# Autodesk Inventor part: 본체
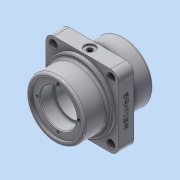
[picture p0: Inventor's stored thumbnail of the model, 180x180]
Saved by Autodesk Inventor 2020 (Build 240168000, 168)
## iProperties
Created: 2023-10
Part Number: 본체
Material: 알루미늄 6061
Document SubType Name: Modeling
Designer: CAD14
Density: 2.7 g/cm^3
Appearance: 흰색
Mass: 945.786 g
Surface Area: 536.974 cm^2
Volume: 350.291 cm^3
Author: CAD14
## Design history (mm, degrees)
sketch "스케치1"
  geometry: L1 (-45, 0)-(45, 0); L2 (-45, 38)-(45, 38); L3 (-45, 38)-(-45, 33); L4 (-45, 33)-(-41, 33); L5 (-41, 33)-(-41, 23.5); L6 (-41, 23.5)-(-24, 23.5); L7 (-24, 23.5)-(-24, 20.5); L8 (-24, 20.5)-(24, 20.5); L9 (24, 20.5)-(24, 23.5); L10 (24, 23.5)-(41, 23.5); L11 (41, 23.5)-(41, 33); L12 (41, 33)-(45, 33); L13 (45, 33)-(45, 38); 2 further points
  constraints: 26 end point, 10 perpendicular, 3 equal length, 2 horizontal, 2 vertical alignment, 1 coincident, 1 midpoint, 1 vertical
  dimensions: "d0" = 90 distance of L1.start L1.end; "d2" = 41 diameter of L8 L1; "d3" = 47 diameter of L6 L1; "d4" = 66 diameter of L4 L1; "d5" = 76 diameter of L2 L1; "d6" = 4 distance between parallel lines of L5 L3; "d7" = 17 distance between parallel lines of L7 L5; "d8" = 17 distance between parallel lines of L9 L11
revolve "회전1" sketch "스케치1" stored, may be unused: angle "d9" = 90 deg
sketch "스케치2"
  geometry: L1 (47, -47)-(-47, -47); L2 (-47, -47)-(-47, 47); L3 (-47, 47)-(47, 47); L4 (47, 47)-(47, -47); L5 (47, -47)-(-47, 47); L6 (-47, -47)-(47, 47); 1 further point
  constraints: 12 end point, 2 midpoint, 2 parallel, 1 horizontal, 1 perpendicular
  dimensions: "d10" = 94 distance of L2.end L3.end; "d11" = 94 distance of L1.end L2.end
extrude "돌출1" join sketch "스케치2" stored distance "d12" = 20; taper "d13" = 0 deg
sketch "스케치3"
  geometry: C1 r 44 at (0, 0); 1 further point
  constraints: 1 centre point, 1 coincident
  dimensions: "d14" = 88 diameter of C1
extrude "돌출2" join sketch "스케치3" distance "d15" = 5; taper "d16" = 0 deg
sketch "스케치4"
  geometry: C1 r 44 at (0, 0); 1 further point
  constraints: 1 centre point, 1 coincident
  dimensions: "d17" = 88 diameter of C1
extrude "돌출3" join sketch "스케치4" distance "d18" = 5; taper "d19" = 0 deg
sketch "스케치5"
  geometry: 1 further point
fillet "모깎기1" dims "d21" = 10
sketch "스케치8"
  geometry: L1 (0, 0)-(0, 27); 1 further point
  constraints: 2 end point, 1 coincident, 1 vertical
  dimensions: "d23" = 27 distance of L1.start L1.end
hole "구멍1" sketch "스케치8" at (0, 27) diameter "d24" = 3.242; stored, may be unused: countersink angle "d28" = 90 deg, drill point angle "d30" = 118 deg; dims "d25" = 8, "d26" = 4, "d27" = 2, "d29" = 10
sketch "스케치9"
  geometry: C1 r 7 at (37, 10); 2 further points
  constraints: 2 coincident, 1 centre point
  dimensions: "d34" = 14 diameter of C1
extrude "돌출4" cut sketch "스케치9" distance "d35" = 2; taper "d36" = 0 deg
sketch "스케치10"
  geometry: C1 r 3.5 at (0, 0); 1 further point
  constraints: 1 centre point, 1 coincident
  dimensions: "d37" = 7 diameter of C1
extrude "돌출5" cut sketch "스케치10" distance "d38" = 2; taper "d39" = 0 deg
sketch "스케치11"
  geometry: C1 r 3.5 at (0, 0) reference; 2 further points
  constraints: 1 coincident
hole "구멍2" sketch "스케치11" at (0, 0) diameter "d40" = 5.1881; stored, may be unused: countersink angle "d44" = 90 deg, drill point angle "d46" = 118 deg; dims "d41" = 12, "d42" = 4, "d43" = 2, "d45" = 16
sketch "스케치12"
  geometry: C1 r 20.5 at (0, 0) reference; C2 r 20.5 at (0, 0); 1 further point
  constraints: 1 centre point, 1 coincident, 1 concentric
extrude "돌출6" cut sketch "스케치12" distance "d47" = 90; taper "d48" = 0 deg
sketch "스케치13"
  geometry: L1 (0, 0)-(63.902, 0); C1 r 3.3 at (37.477, 37.477); 1 further point
  constraints: 2 end point, 1 centre point, 1 coincident, 1 horizontal
  dimensions: "d52" = 6.6 diameter of C1
extrude "돌출7" cut sketch "스케치13" stored distance "d54" = 20; taper "d55" = 0 deg
sketch "스케치14"
  geometry: C1 r 3.3 at (-37.477, 37.477) reference; C2 r 5.5 at (-37.477, 37.477); 1 further point
  constraints: 1 centre point, 1 coincident
  dimensions: "d56" = 11 diameter of C2
extrude "돌출8" cut sketch "스케치14" distance "d57" = 7; taper "d58" = 0 deg
sketch "스케치15"
  geometry: L1 (0, 0)-(-74, 0) reference; 2 further points
  constraints: 1 coincident, 1 other
  dimensions: "d59" = 10 distance from line of L1 point (-37, 10)
feature "엠보싱1" sketch "스케치15" dims "d10" = 94, "d11" = 94, "d60" = 0.5, "d61" = 0
fillet "모깎기2" dims "d62" = 3
chamfer "모따기1" distance "d63" = 1; stored, may be unused: second distance "d64" = 2, angle "d65" = 45 deg
fillet "모깎기3" dims "d66" = 3
chamfer "모따기2" distance "d67" = 1; stored, may be unused: second distance "d68" = 2, angle "d69" = 45 deg
fillet "모깎기4" dims "d70" = 1
sketch "스케치16"
  geometry: C1 r 3.3 at (37.477, -37.477) reference; C2 r 3.3 at (37.477, 37.477) reference; C3 r 3.3 at (-37.477, 37.477) reference; C4 r 5.5 at (37.477, -37.477) reference; C5 r 5.5 at (37.477, -37.477); C6 r 5.5 at (37.477, 37.477) reference; C7 r 5.5 at (37.477, 37.477); C8 r 5.5 at (-37.477, 37.477) reference; C9 r 5.5 at (-37.477, 37.477); 1 further point
  constraints: 3 centre point, 3 coincident
  dimensions: "d71" = 11 diameter of C5; "d72" = 11 diameter of C7; "d73" = 11 diameter of C9
extrude "돌출9" cut sketch "스케치16" distance "d74" = 7; taper "d75" = 0 deg
node "솔리드1"
pattern_circular "원형 패턴1" dims angle "d32" = 360 deg
mirror "미러1"
mirror "미러2"
mirror "미러3"
mirror "미러4"
feature "A9D066F2-1C7D-4E18-AEED-F7BC21143FA4" dims "d24" = 3.242, "d25" = 8, "d26" = 4, "d27" = 2, "d28" = 90 deg, "d29" = 10, "d30" = 118 deg
